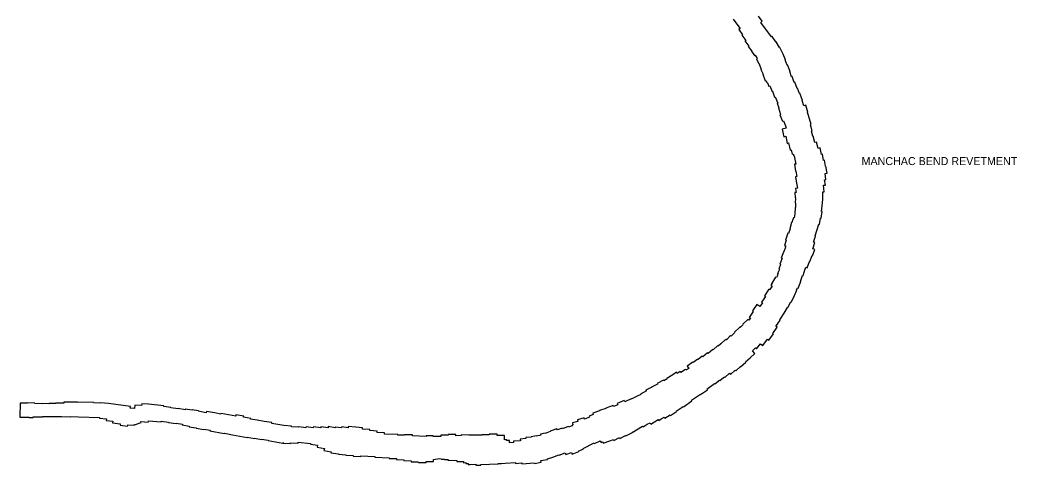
# Model space of a CAD drawing. Extents: x 2650582 to 3923188, y 277893 to 989177.
# Drawn here: x 3326831 to 3346770, y 658529 to 667439 of the extents above; entities that cross this region are included whole.
import ezdxf

# ---------------------------------------------------------------- set-up
doc = ezdxf.new("R2010")
doc.units = 0
doc.layers.add('Level 3', color=7, linetype='Continuous')

msp = doc.modelspace()

# ---------------------------------------------------------------- linework, layer by layer
at = {"layer": 'Level 3'}
msp.add_line((3340174, 660508), (3340207, 660463), dxfattribs=at)
for points in [[(3341091, 667456), (3341167, 667352), (3341169, 667354), (3341235, 667265), (3341209, 667246), (3341283, 667141), (3341269, 667131), (3341344, 667030)], [(3341645, 667390), (3341671, 667412), (3341598, 667513)], [(3342545, 662489), (3342570, 662479), (3342620, 662605), (3342628, 662602), (3342673, 662721), (3342680, 662718), (3342728, 662846), (3342689, 662859), (3342728, 662985), (3342699, 662994), (3342737, 663114), (3342732, 663115), (3342808, 663349), (3342817, 663347), (3342843, 663469), (3342850, 663468), (3342874, 663603), (3342861, 663606), (3342874, 663720), (3342884, 663848), (3342888, 663995), (3342910, 663997), (3342900, 664129), (3342939, 664134), (3342922, 664239), (3342948, 664245), (3342931, 664367), (3342972, 664374), (3342949, 664511), (3342938, 664509), (3342918, 664630), (3342899, 664627), (3342879, 664749), (3342861, 664745), (3342833, 664877), (3342790, 664867), (3342760, 664994), (3342728, 664984), (3342693, 665111), (3342689, 665110), (3342658, 665212), (3342673, 665217), (3342639, 665340), (3342656, 665345), (3342579, 665592), (3342585, 665594), (3342544, 665731), (3342507, 665718), (3342473, 665823), (3342478, 665825), (3342427, 665970), (3342419, 665966), (3342380, 666072), (3342373, 666069), (3342325, 666193), (3342313, 666188), (3342273, 666304), (3342263, 666300), (3342226, 666405), (3342230, 666406), (3342182, 666539), (3342171, 666535), (3342131, 666639), (3342138, 666643), (3342090, 666751), (3342025, 666888), (3342021, 666886), (3341953, 667003), (3341946, 666999), (3341871, 667106), (3341863, 667101), (3341788, 667202), (3341784, 667198), (3341718, 667288), (3341720, 667290), (3341645, 667390)], [(3341344, 667030), (3341329, 667019), (3341405, 666916), (3341395, 666909), (3341465, 666815), (3341460, 666811), (3341522, 666724), (3341531, 666731), (3341571, 666664), (3341562, 666659), (3341609, 666557), (3341611, 666558), (3341655, 666450)], [(3341655, 666450), (3341647, 666446), (3341692, 666355), (3341687, 666353), (3341733, 666223), (3341747, 666228), (3341770, 666177), (3341780, 666182), (3341804, 666116), (3341805, 666117), (3341806, 666113), (3341829, 666122)], [(3341829, 666122), (3341874, 666008), (3341879, 666010), (3341923, 665893), (3341936, 665898), (3341984, 665773), (3341976, 665770), (3342008, 665682), (3341997, 665677), (3342042, 665548), (3342027, 665542), (3342080, 665411), (3342099, 665420), (3342140, 665320), (3342154, 665270)], [(3342154, 665270), (3342076, 665254), (3342106, 665102), (3342146, 665111), (3342175, 664969), (3342201, 664976), (3342236, 664833), (3342251, 664837), (3342271, 664753), (3342290, 664757)], [(3342290, 664757), (3342308, 664716), (3342314, 664719), (3342345, 664554), (3342320, 664550), (3342339, 664409), (3342348, 664410), (3342364, 664303), (3342343, 664299), (3342362, 664169), (3342360, 664169), (3342377, 664071), (3342343, 664065), (3342352, 663986), (3342329, 663984), (3342330, 663879), (3342337, 663878), (3342331, 663771), (3342339, 663770), (3342339, 663683), (3342334, 663682), (3342325, 663558), (3342312, 663478), (3342300, 663479), (3342287, 663439), (3342281, 663439)], [(3342281, 663439), (3342276, 663407), (3342269, 663385), (3342260, 663386), (3342224, 663261), (3342230, 663259), (3342199, 663164), (3342185, 663169), (3342139, 663034), (3342150, 663029), (3342121, 662923), (3342144, 662916)], [(3342144, 662916), (3342133, 662889), (3342137, 662887), (3342106, 662806), (3342108, 662806), (3342055, 662675), (3342073, 662668), (3342025, 662549)], [(3342025, 662549), (3342042, 662541), (3342005, 662448), (3342018, 662444), (3341985, 662380), (3341992, 662376), (3341976, 662342), (3341988, 662335), (3341960, 662283), (3341943, 662293), (3341861, 662159), (3341867, 662155), (3341847, 662122), (3341871, 662107), (3341823, 662038), (3341808, 662047), (3341721, 661917), (3341737, 661905), (3341660, 661793), (3341678, 661779), (3341625, 661703)], [(3342381, 662077), (3342392, 662073), (3342446, 662201), (3342439, 662205), (3342483, 662327), (3342491, 662324), (3342533, 662454), (3342535, 662453), (3342545, 662489)], [(3342024, 661437), (3342114, 661568), (3342116, 661567), (3342177, 661684), (3342185, 661680), (3342246, 661800), (3342258, 661795), (3342317, 661925), (3342321, 661922), (3342364, 662028), (3342360, 662029), (3342381, 662077)], [(3341625, 661703), (3341565, 661744), (3341479, 661616), (3341495, 661604), (3341414, 661486), (3341437, 661470), (3341406, 661429), (3341389, 661446), (3341290, 661347), (3341294, 661343), (3341245, 661299), (3341240, 661302), (3341225, 661283), (3341223, 661285), (3341119, 661191), (3341126, 661183), (3341107, 661160), (3341052, 661111), (3341039, 661123), (3340973, 661049), (3340950, 661028), (3340939, 661040), (3340847, 660956), (3340846, 660957), (3340793, 660910)], [(3341527, 660761), (3341477, 660817), (3341541, 660874), (3341560, 660858), (3341641, 660958), (3341689, 660923), (3341780, 661048), (3341807, 661029), (3341899, 661153), (3341888, 661161), (3341976, 661287), (3341949, 661307), (3341989, 661356), (3341985, 661360), (3342033, 661431), (3342024, 661437)], [(3340793, 660910), (3340785, 660920), (3340691, 660839), (3340685, 660844), (3340591, 660763), (3340578, 660777), (3340485, 660697), (3340471, 660712), (3340392, 660644), (3340386, 660651), (3340295, 660580), (3340287, 660590), (3340174, 660508)], [(3339282, 659308), (3339292, 659293), (3339374, 659348), (3339431, 659376), (3339449, 659349), (3339593, 659442), (3339605, 659422), (3339653, 659454), (3339713, 659486), (3339725, 659468), (3339831, 659538), (3339840, 659525), (3339959, 659603), (3339955, 659610), (3340096, 659699), (3340098, 659696), (3340270, 659816), (3340262, 659828), (3340439, 659950), (3340443, 659944), (3340577, 660036), (3340569, 660050), (3340722, 660164), (3340729, 660156), (3340818, 660230), (3340827, 660220), (3340868, 660258), (3340917, 660295), (3340926, 660285), (3341019, 660369), (3341040, 660345), (3341133, 660429), (3341144, 660417), (3341237, 660500), (3341240, 660497), (3341344, 660591), (3341342, 660593), (3341435, 660676), (3341434, 660677), (3341527, 660761)], [(3340207, 660463), (3340148, 660427), (3340138, 660442), (3340045, 660384), (3340036, 660400), (3339975, 660364)], [(3339975, 660364), (3339957, 660389), (3339886, 660337), (3339885, 660338), (3339768, 660262), (3339773, 660254), (3339705, 660213), (3339698, 660226), (3339574, 660159), (3339579, 660149), (3339463, 660087), (3339464, 660086), (3339349, 660026), (3339357, 660013), (3339242, 659951), (3339246, 659944), (3339172, 659907)], [(3339172, 659907), (3339171, 659908), (3339055, 659847), (3339051, 659857), (3338928, 659796), (3338916, 659824), (3338774, 659760), (3338786, 659732), (3338701, 659699), (3338691, 659723), (3338545, 659668), (3338547, 659662), (3338421, 659620), (3338422, 659616), (3338287, 659568), (3338297, 659540)], [(3326837, 659770), (3326831, 659486), (3327015, 659485), (3327015, 659482), (3327096, 659484), (3327095, 659493), (3327284, 659494), (3327284, 659502), (3327663, 659504), (3327663, 659499), (3327834, 659496), (3327835, 659504), (3327999, 659498), (3327999, 659492), (3328422, 659483), (3328421, 659465), (3328560, 659455), (3328557, 659423), (3328690, 659410), (3328685, 659376), (3328838, 659355), (3328835, 659331), (3328985, 659309), (3328989, 659337), (3329114, 659331), (3329116, 659343), (3329119, 659333), (3329256, 659381), (3329251, 659399), (3329395, 659385), (3329399, 659418), (3329652, 659398), (3329653, 659411), (3329800, 659389), (3329800, 659384), (3329953, 659362), (3329954, 659367), (3330080, 659347), (3330077, 659334), (3330216, 659309), (3330214, 659296), (3330353, 659272), (3330353, 659267), (3330508, 659240)], [(3331868, 659379), (3331716, 659404), (3331715, 659399), (3331572, 659426), (3331444, 659448), (3331446, 659462), (3331302, 659488), (3331305, 659506), (3331150, 659534), (3331146, 659511), (3330853, 659564), (3330850, 659550), (3330724, 659573), (3330724, 659577), (3330563, 659605), (3330558, 659578), (3330398, 659606), (3330399, 659614), (3330277, 659637), (3330276, 659627), (3330135, 659650), (3330133, 659638), (3329998, 659659), (3329996, 659653), (3329850, 659677), (3329851, 659681), (3329706, 659705), (3329706, 659714), (3329402, 659746), (3329402, 659748), (3329270, 659757), (3329265, 659719), (3329130, 659729), (3329123, 659663), (3329037, 659671), (3329042, 659705), (3328600, 659759), (3328600, 659765), (3328443, 659775), (3328443, 659766), (3328299, 659773), (3328298, 659786), (3327980, 659783), (3327980, 659789), (3327711, 659791), (3327710, 659768), (3327551, 659768), (3327551, 659763), (3327418, 659764), (3327418, 659758), (3327280, 659760), (3327280, 659758), (3327129, 659760), (3327129, 659770), (3326981, 659773), (3326981, 659767), (3326837, 659770)], [(3338297, 659540), (3338211, 659509), (3338220, 659485), (3338120, 659449), (3338111, 659477), (3337978, 659433), (3337988, 659401), (3337878, 659372), (3337888, 659337)], [(3330508, 659240), (3330510, 659247), (3330632, 659225), (3330630, 659218), (3330918, 659163), (3330920, 659170), (3331084, 659138), (3331083, 659134), (3331231, 659107), (3331231, 659105), (3331374, 659079), (3331375, 659088), (3331520, 659060), (3331521, 659065), (3331661, 659038), (3331663, 659046), (3331796, 659025), (3331795, 659018), (3332089, 658970), (3332092, 658979), (3332092, 658971), (3332244, 658960), (3332244, 658976), (3332392, 658966), (3332393, 658991), (3332641, 658963), (3332640, 658950), (3332781, 658926), (3332777, 658889), (3332918, 658864), (3332911, 658818), (3333052, 658794), (3333050, 658776), (3333200, 658755), (3333200, 658749), (3333347, 658736), (3333347, 658727), (3333492, 658719), (3333492, 658711), (3333648, 658702), (3333649, 658714), (3333930, 658701), (3333929, 658688), (3334216, 658673), (3334216, 658663), (3334362, 658659), (3334362, 658640), (3334510, 658636), (3334509, 658620), (3334652, 658615), (3334652, 658597), (3334797, 658593), (3334798, 658584), (3334954, 658581), (3334954, 658603), (3335101, 658604), (3335101, 658643), (3335223, 658658), (3335251, 658656)], [(3335249, 659100), (3335096, 659099), (3335096, 659112), (3334956, 659112), (3334957, 659104), (3334680, 659113), (3334679, 659133), (3334520, 659137), (3334521, 659128), (3334386, 659131), (3334386, 659140), (3334118, 659151), (3334118, 659173), (3333972, 659183), (3333973, 659209), (3333829, 659221), (3333830, 659239), (3333679, 659250), (3333680, 659275), (3333545, 659285), (3333545, 659291), (3333395, 659299), (3333393, 659278), (3333265, 659293), (3333262, 659273), (3333135, 659290), (3333133, 659276), (3332997, 659299), (3332992, 659274), (3332850, 659296), (3332846, 659272), (3332702, 659295), (3332697, 659272), (3332553, 659292), (3332551, 659278), (3332405, 659295), (3332404, 659288), (3332259, 659298), (3332259, 659305), (3332105, 659323), (3332106, 659321), (3331866, 659360), (3331868, 659379)], [(3335945, 658546), (3335947, 658530), (3336046, 658529), (3336046, 658539), (3336394, 658554), (3336394, 658560), (3336461, 658564), (3336461, 658562), (3336536, 658566), (3336536, 658569), (3336742, 658582), (3336744, 658562), (3336866, 658575), (3336869, 658556), (3337122, 658575), (3337124, 658561), (3337256, 658588), (3337250, 658619), (3337381, 658643), (3337379, 658655), (3337489, 658689), (3337488, 658691), (3337609, 658735), (3337612, 658728), (3337731, 658772), (3337744, 658738), (3337860, 658781), (3337871, 658751), (3338004, 658800), (3338001, 658808), (3338099, 658853), (3338094, 658863), (3338313, 658972), (3338319, 658959), (3338436, 659013), (3338451, 658980), (3338487, 658996), (3338497, 658969), (3338627, 659017), (3338628, 659014), (3338698, 659038), (3338704, 659024), (3338820, 659079), (3338827, 659064), (3338943, 659120), (3338947, 659114), (3339080, 659180), (3339077, 659184), (3339282, 659308)], [(3337888, 659337), (3337872, 659330), (3337877, 659317), (3337803, 659287), (3337797, 659302), (3337681, 659258), (3337677, 659269), (3337578, 659232), (3337569, 659256), (3337435, 659206), (3337437, 659199), (3337335, 659161), (3337332, 659169), (3337242, 659145), (3337247, 659126), (3337160, 659109), (3337159, 659113), (3337053, 659095), (3337054, 659089), (3336946, 659081), (3336948, 659060), (3336836, 659047), (3336839, 659016), (3336699, 659006), (3336701, 658979), (3336624, 658974), (3336623, 659022), (3336564, 659018), (3336561, 659038), (3336520, 659035)], [(3336520, 659035), (3336518, 659124), (3336375, 659119), (3336374, 659151), (3336216, 659147), (3336216, 659138), (3336076, 659135), (3336076, 659126), (3335811, 659126), (3335810, 659131), (3335657, 659134), (3335656, 659119), (3335548, 659117), (3335548, 659139), (3335392, 659139), (3335391, 659131), (3335249, 659131), (3335249, 659100)], [(3335251, 658656), (3335251, 658651), (3335321, 658650), (3335321, 658641), (3335391, 658640), (3335390, 658629), (3335566, 658624), (3335566, 658598), (3335699, 658599), (3335700, 658576), (3335749, 658579), (3335750, 658560), (3335795, 658561), (3335796, 658541), (3335829, 658543), (3335829, 658539), (3335945, 658546)]]:
    msp.add_lwpolyline(points, dxfattribs=at)

# ---------------------------------------------------------------- texts
msp.add_text('MANCHAC BEND REVETMENT', height=160, dxfattribs=at).set_placement((3343661, 664534))

doc.saveas('drawing.dxf')
